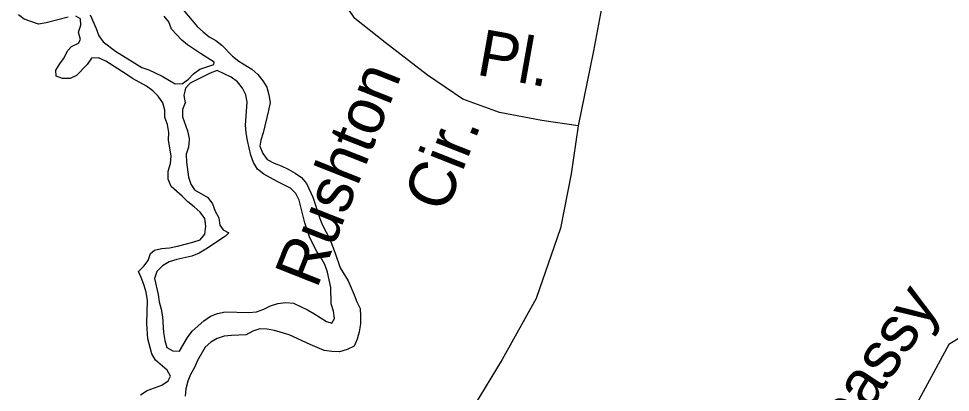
# Model space of a CAD drawing. Extents: x 2290055 to 2389491, y 66597 to 237875.
# Drawn here: x 2325346 to 2327254, y 150567 to 151332 of the extents above; entities that cross this region are included whole.
import ezdxf

# ---------------------------------------------------------------- set-up
doc = ezdxf.new("R2010")
doc.units = 0
for name, color, linetype in [('Exist Hydrographic Creek Double Shore', 7, 'Continuous'), ('Exist Road Non-System Type 51', 7, 'Continuous'), ('Exist Road Non-System Type 51 Label', 7, 'Continuous')]:
    doc.layers.add(name, color=color, linetype=linetype)

msp = doc.modelspace()

# ---------------------------------------------------------------- linework, layer by layer
at = {"layer": 'Exist Hydrographic Creek Double Shore'}
for points in [[(2325448.2, 151334.9), (2325403.2, 151323.7), (2325387.2, 151321), (2325358, 151331.3), (2325346.5, 151339.8)], [(2325492.7, 151340), (2325505.5, 151312.1), (2325510.5, 151296.9), (2325519.7, 151284.3), (2325544.7, 151265.5), (2325598.5, 151232.2), (2325613, 151227), (2325640.5, 151214), (2325667.2, 151198.8), (2325682.2, 151199.4), (2325694.5, 151208), (2325704.7, 151219.2), (2325717.2, 151228.7), (2325746.2, 151238.1), (2325746.7, 151243.1), (2325719, 151260.5), (2325692.5, 151278.4), (2325680.5, 151287.7), (2325659.5, 151310.6), (2325654, 151325.4), (2325644.5, 151337.5)], [(2325683.7, 151350.4), (2325713, 151315), (2325724.5, 151304.8), (2325736.7, 151294.8), (2325750.2, 151287.1), (2325762.5, 151277.9), (2325784.7, 151255.5), (2325797.5, 151245.1), (2325824, 151228.6), (2325836.2, 151217.6), (2325846.5, 151204.8), (2325854.7, 151191.8), (2325859, 151176.3), (2325861.2, 151160.1), (2325858.2, 151144), (2325847.5, 151098.4), (2325842.5, 151083.5), (2325840.5, 151070.8), (2325846.7, 151056.1), (2325855.7, 151043.9), (2325869.5, 151036.2), (2325884, 151030.6), (2325898.7, 151023.7), (2325912.7, 151015.3), (2325925.7, 151006.8), (2325936, 150994.6), (2325948.7, 150966.4), (2325963.2, 150923), (2325968.7, 150908.8), (2325983.5, 150880.7), (2325994.7, 150852.1), (2326004.5, 150821.9), (2326021.5, 150795.1), (2326033.7, 150766.6), (2326039, 150751.9), (2326045.7, 150738.2), (2326046.7, 150722.5), (2326046.2, 150706.7)], [(2325566.7, 151218.6), (2325525, 151245.1), (2325510, 151251.6), (2325495.5, 151251.4), (2325487, 151238.5), (2325465.2, 151215.5), (2325451.7, 151209.2), (2325436, 151209.7), (2325423.2, 151214.5), (2325422.7, 151226.4), (2325430.7, 151239.4), (2325439.7, 151251.5), (2325446.5, 151266.2), (2325455, 151274.8), (2325469, 151282.1), (2325473.5, 151289.2), (2325469.2, 151304.4), (2325474, 151318.9), (2325473, 151331.4), (2325463.5, 151337)], [(2325676, 150651.3), (2325692.2, 150678.8), (2325702, 150691.7), (2325726, 150713.5), (2325739, 150723), (2325753.5, 150728.1), (2325769.7, 150731.5), (2325817.7, 150730.1), (2325833.5, 150731.5), (2325848.5, 150736.9), (2325862.2, 150744), (2325877.5, 150749), (2325893.7, 150750.8), (2325909, 150749.5), (2325937.7, 150735.9), (2325951.2, 150728.5), (2325977, 150711.7), (2325988, 150708.2), (2325993, 150717.7), (2325991.2, 150733), (2325986.2, 150748.1), (2325985.7, 150781.2), (2325978.7, 150813.1), (2325973.5, 150828.8), (2325965.5, 150842.7), (2325957, 150855.3), (2325943, 150883.1), (2325932.7, 150914.1), (2325921.2, 150960.1), (2325914.2, 150973.8), (2325903, 150984.9), (2325875.7, 150998.6), (2325848.2, 151013.6), (2325835.5, 151024.1), (2325827.5, 151037.4), (2325822, 151052.5), (2325815, 151082.7), (2325812.2, 151098), (2325810.7, 151114.1), (2325814.5, 151160.9), (2325811.5, 151176.1), (2325805, 151189.7), (2325794.5, 151202.4), (2325781.5, 151212.2), (2325752.7, 151225.7), (2325738.5, 151220.3), (2325697.5, 151199.8), (2325688, 151189.8), (2325684.5, 151174.8), (2325687.5, 151159.9), (2325682.2, 151146.2), (2325682.2, 151131.1), (2325692, 151102.1), (2325695.5, 151086.8), (2325695.5, 151083.7), (2325694.5, 151068.7), (2325689.7, 151054.2), (2325690.5, 151038), (2325694.2, 151007.5), (2325699, 150992.8), (2325706.7, 150981.2), (2325734, 150965.6), (2325743.2, 150952.7), (2325748.7, 150938.1), (2325756.2, 150924), (2325758.5, 150908.9), (2325765.5, 150899.4), (2325777, 150893.1), (2325770, 150886.5), (2325729.7, 150860), (2325716, 150851.9), (2325701.2, 150845.8), (2325670.5, 150838.7), (2325655, 150834), (2325641.2, 150825.6), (2325629.7, 150814.1), (2325624.7, 150799.8), (2325632, 150767.4), (2325634, 150752.4), (2325638.2, 150736.8), (2325641.2, 150721.1), (2325643.2, 150689.1), (2325645.5, 150672.9), (2325650.2, 150658.5), (2325662, 150651.7), (2325676, 150651.3)], [(2325596.2, 150561.9), (2325610, 150570.3), (2325639.7, 150581.4), (2325652.7, 150590.4), (2325657.2, 150600), (2325650.7, 150612.1), (2325626.5, 150632.5), (2325619, 150645.6), (2325610.7, 150676.5), (2325609, 150707.6), (2325610.2, 150754.8), (2325607.7, 150771.8), (2325603, 150787.9), (2325597.7, 150802.1), (2325591.7, 150814.1), (2325602.7, 150824.9), (2325611.7, 150837), (2325616.7, 150851.2), (2325624.5, 150858), (2325639, 150861.5), (2325655.5, 150862.9), (2325671.5, 150865.8), (2325703, 150874), (2325718, 150879), (2325727.5, 150890.9), (2325730, 150906.9), (2325727.5, 150923.1), (2325718.5, 150935.5), (2325706.2, 150947), (2325693, 150957.2), (2325681.5, 150968.5), (2325659, 150988.6), (2325652.5, 151003.5), (2325652.7, 151019.8), (2325657.2, 151035.6), (2325658.5, 151051.3), (2325653.5, 151083.3), (2325653.7, 151098.7), (2325651, 151115), (2325645.7, 151129.6), (2325645.5, 151144.7), (2325641.5, 151159.5), (2325632, 151173.1), (2325621.2, 151184), (2325608.2, 151193.5), (2325579.7, 151209.4), (2325566.7, 151218.6)], [(2326046.2, 150706.7), (2326044, 150690.9), (2326039.5, 150675.5), (2326033.2, 150661.4), (2326019, 150654.5), (2326003.5, 150650), (2325988, 150650.1), (2325972.2, 150652.3), (2325943.5, 150664.4), (2325900.2, 150684.2), (2325870.5, 150693.3), (2325855.7, 150695.8), (2325840.5, 150696.7), (2325826.2, 150691.9), (2325812.7, 150684.6), (2325782.5, 150683.2), (2325767.5, 150681.6), (2325753.2, 150676.8), (2325739.7, 150669.4), (2325728.2, 150659.4), (2325712.5, 150631.8), (2325706.5, 150617.8), (2325698.7, 150603.6), (2325692.7, 150589.3), (2325689, 150574.2), (2325687.5, 150559.2)]]:
    msp.add_lwpolyline(points, dxfattribs=at)
at = {"layer": 'Exist Road Non-System Type 51'}
for points in [[(2326492.2, 151112.7), (2326417.6, 151123.6), (2326330.9, 151140.2), (2326255.7, 151167.4), (2326183.8, 151216.4), (2326097.2, 151283.2), (2326035.1, 151332.6), (2325990.5, 151398.8), (2325967.9, 151464.2), (2325953.1, 151531.5), (2325935.5, 151629), (2325933, 151740.8)], [(2326469.3, 151692.1), (2326513.4, 151637.7), (2326548.9, 151544.9), (2326558.9, 151491.5), (2326550.3, 151409.1), (2326523.8, 151265.9), (2326492.2, 151112.7)], [(2326492.2, 151112.7), (2326478, 151014), (2326456.1, 150903.2), (2326406, 150759.1), (2326336.8, 150634.3), (2326278.6, 150538.2), (2326253.3, 150470.9), (2326224.7, 150381.8)], [(2327366.1, 150735.5), (2327251.2, 150664.8), (2327171.7, 150518.9), (2327105.4, 150381.8), (2327126.8, 150184.1)]]:
    msp.add_lwpolyline(points, dxfattribs=at)

# ---------------------------------------------------------------- texts
at = {"layer": 'Exist Road Non-System Type 51 Label'}
for s, rotation, p in [('Pl.', 349.9089, (2326281.5, 151217.6)), ('Rushton', 68.3904, (2325957, 150777)), ('Cir.', 68.3904, (2326220.9, 150931.3)), ('Embassy', 56.498, (2326944.6, 150310.4))]:
    msp.add_text(s, height=95, rotation=rotation, dxfattribs=at).set_placement(p)

doc.saveas('drawing.dxf')
